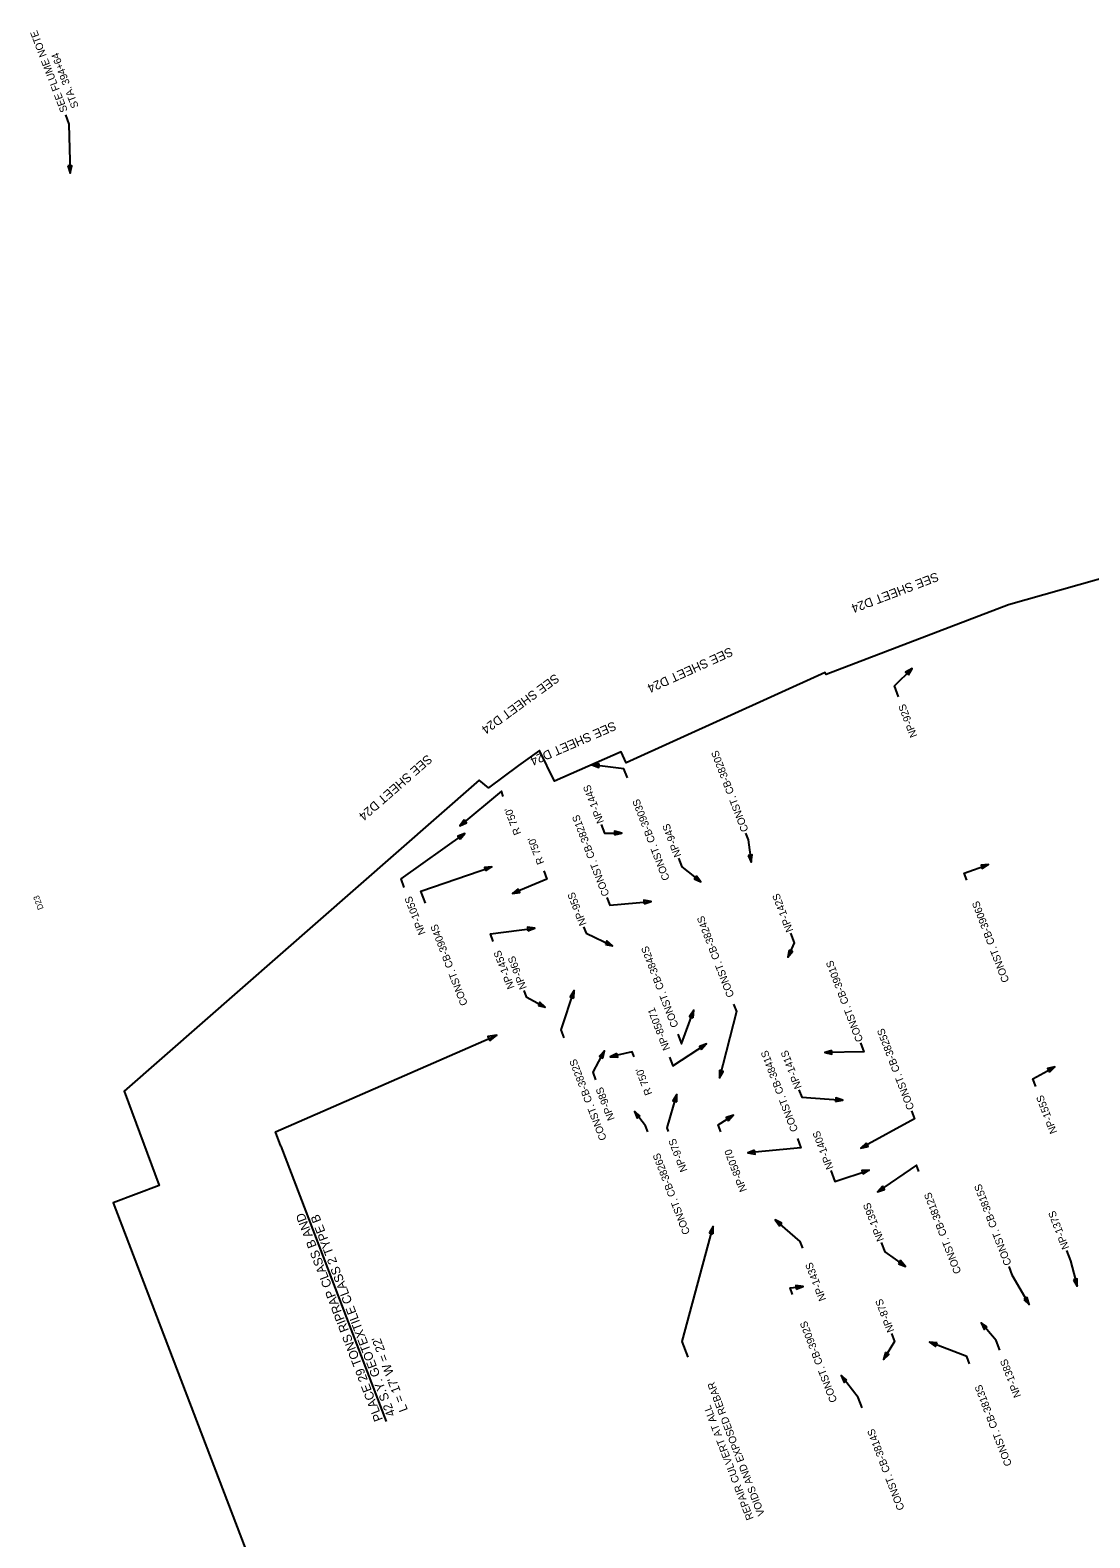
# Model space of a CAD drawing. Extents: x 1611058 to 1612754, y 1091411 to 1093437.
# Drawn here: x 1611058 to 1611771, y 1092422 to 1093437 of the extents above; entities that cross this region are included whole.
import ezdxf

# ---------------------------------------------------------------- set-up
doc = ezdxf.new("R2010")
doc.units = 0
for name, color, linetype in [('BR_CONCRETE', 7, 'Continuous'), ('RD_HC_CL', 7, 'Continuous'), ('RD_HY_Area_XP-Post sub TXT', 7, 'Continuous'), ('RD_HY_Misc', 7, 'Continuous')]:
    doc.layers.add(name, color=color, linetype=linetype)

msp = doc.modelspace()

# ---------------------------------------------------------------- linework, layer by layer
at = {"layer": 'BR_CONCRETE'}
msp.add_line((1611227, 1092685.9), (1611297.8, 1092500.6), dxfattribs=at)
for points in [[(1611082, 1093379.7), (1611084.3, 1093373.4), (1611085.1, 1093340.5)], [(1611642.6, 1092988.1), (1611639.8, 1092995.5), (1611651.7, 1093007.2)], [(1611460.1, 1092933.6), (1611457.7, 1092939.8), (1611436.2, 1092942.4)], [(1611376.6, 1092921.1), (1611375.3, 1092924.6), (1611347.4, 1092901.3)], [(1611442.5, 1092902.2), (1611444.8, 1092896.4), (1611456.3, 1092896.5)], [(1611310, 1092859.9), (1611307.8, 1092865.6), (1611350.7, 1092896.3)], [(1611539.7, 1092896.5), (1611541.5, 1092891.9), (1611543.4, 1092876.9)], [(1611324.2, 1092849.3), (1611321.1, 1092857.4), (1611369, 1092873.8)], [(1611403.8, 1092871), (1611405.9, 1092865.5), (1611382.8, 1092855.8)], [(1611494.5, 1092879.6), (1611496.8, 1092873.7), (1611509.5, 1092863.6)], [(1611688.5, 1092864.9), (1611686.8, 1092869.6), (1611703.1, 1092875.3)], [(1611446.2, 1092853.2), (1611448.2, 1092848), (1611476.2, 1092850.5)], [(1611369.9, 1092823.5), (1611367.9, 1092828.6), (1611397.8, 1092832.6)], [(1611430.7, 1092833.4), (1611432.3, 1092829.2), (1611450.2, 1092820.6)], [(1611569.8, 1092829.2), (1611572.3, 1092822.7), (1611568.1, 1092812.9)], [(1611390.5, 1092790.5), (1611392.1, 1092786.4), (1611404.8, 1092779.3)], [(1611417.6, 1092758.7), (1611415.6, 1092764.1), (1611424.4, 1092790.5)], [(1611531.6, 1092781.5), (1611533.5, 1092776.5), (1611522, 1092731.9)], [(1611494.1, 1092761.3), (1611496.6, 1092754.6), (1611504.8, 1092777.3)], [(1611227, 1092685.9), (1611223.3, 1092695.6), (1611372.2, 1092760.6)], [(1611439, 1092730.4), (1611437, 1092735.7), (1611444.7, 1092749.9)], [(1611464.7, 1092745.9), (1611463.4, 1092749.4), (1611448.6, 1092745.9)], [(1611488.4, 1092745.8), (1611490.7, 1092739.8), (1611513.4, 1092754.6)], [(1611617, 1092755.3), (1611619.2, 1092749.3), (1611592.9, 1092748.9)], [(1611735, 1092726.1), (1611733, 1092731.1), (1611747.8, 1092739.2)], [(1611487.9, 1092695.7), (1611487, 1092698.1), (1611493.4, 1092720.6)], [(1611575.6, 1092723.7), (1611577.4, 1092718.9), (1611605.1, 1092716.7)], [(1611473.8, 1092695.4), (1611472.3, 1092699.5), (1611464.9, 1092709.2)], [(1611651.3, 1092709.6), (1611653.4, 1092704.2), (1611617.3, 1092684.5)], [(1611522.9, 1092695.5), (1611521.1, 1092700.3), (1611531.5, 1092706.6)], [(1611574.5, 1092691), (1611576.9, 1092684.8), (1611541.1, 1092681.3)], [(1611597, 1092669.5), (1611599.8, 1092662), (1611622.9, 1092669.8)], [(1611656.3, 1092668.9), (1611654.7, 1092673), (1611628.5, 1092655.2)], [(1611501, 1092544), (1611497, 1092554.5), (1611517.9, 1092631.8)], [(1611578.1, 1092617.3), (1611576.4, 1092621.7), (1611559.6, 1092636.3)], [(1611630.9, 1092621), (1611633.3, 1092614.8), (1611647.2, 1092605)], [(1611755.5, 1092615.6), (1611758.2, 1092608.8), (1611762.8, 1092591.7)], [(1611716.7, 1092604.9), (1611718.9, 1092599.2), (1611730.4, 1092579.3)], [(1611571.3, 1092586.1), (1611569.6, 1092590.6), (1611578.3, 1092591.4)], [(1611710.7, 1092548.6), (1611708.2, 1092555.1), (1611698.1, 1092567.1)], [(1611637.8, 1092559.9), (1611639.9, 1092554.5), (1611632.5, 1092542.3)], [(1611690.3, 1092539.5), (1611688.5, 1092544.4), (1611663.5, 1092554)], [(1611618.1, 1092509.8), (1611615.4, 1092516.8), (1611603.9, 1092531.5)]]:
    msp.add_lwpolyline(points, dxfattribs=at)
for points in [[(1611083.7, 1093345.3), (1611085.1, 1093340.5), (1611086.3, 1093345.3)], [(1611649.2, 1093002.9), (1611651.7, 1093007.2), (1611647.3, 1093004.7)], [(1611441.1, 1092943.1), (1611436.2, 1092942.4), (1611440.8, 1092940.6)], [(1611350.3, 1092905.4), (1611347.4, 1092901.3), (1611351.9, 1092903.4)], [(1611347.6, 1092892.4), (1611350.7, 1092896.3), (1611346.1, 1092894.5)], [(1611451.5, 1092895.2), (1611456.3, 1092896.5), (1611451.4, 1092897.8)], [(1611541.5, 1092881.5), (1611543.4, 1092876.9), (1611544.1, 1092881.9)], [(1611364.9, 1092871), (1611369, 1092873.8), (1611364, 1092873.4)], [(1611698.9, 1092872.5), (1611703.1, 1092875.3), (1611698.1, 1092874.9)], [(1611505, 1092865.6), (1611509.5, 1092863.6), (1611506.6, 1092867.6)], [(1611386.7, 1092858.9), (1611382.8, 1092855.8), (1611387.7, 1092856.5)], [(1611471.5, 1092848.8), (1611476.2, 1092850.5), (1611471.2, 1092851.3)], [(1611393.2, 1092830.7), (1611397.8, 1092832.6), (1611392.9, 1092833.3)], [(1611445.3, 1092821.5), (1611450.2, 1092820.6), (1611446.4, 1092823.9)], [(1611568.9, 1092817.8), (1611568.1, 1092812.9), (1611571.2, 1092816.8)], [(1611424.1, 1092785.5), (1611424.4, 1092790.5), (1611421.7, 1092786.3)], [(1611400, 1092780.5), (1611404.8, 1092779.3), (1611401.2, 1092782.7)], [(1611504.4, 1092772.3), (1611504.8, 1092777.3), (1611501.9, 1092773.2)], [(1611367.5, 1092756.8), (1611372.2, 1092760.6), (1611366.2, 1092759.7)], [(1611443.6, 1092745), (1611444.7, 1092749.9), (1611441.3, 1092746.3)], [(1611453, 1092748.3), (1611448.6, 1092745.9), (1611453.6, 1092745.8)], [(1611510.1, 1092750.8), (1611513.4, 1092754.6), (1611508.6, 1092753)], [(1611597.7, 1092750.2), (1611592.9, 1092748.9), (1611597.7, 1092747.7)], [(1611744.2, 1092735.7), (1611747.8, 1092739.2), (1611742.9, 1092738)], [(1611522, 1092736.9), (1611522, 1092731.9), (1611524.5, 1092736.2)], [(1611493.3, 1092715.6), (1611493.4, 1092720.6), (1611490.8, 1092716.3)], [(1611600.1, 1092715.8), (1611605.1, 1092716.7), (1611600.4, 1092718.4)], [(1611468.8, 1092706.1), (1611464.9, 1092709.2), (1611466.8, 1092704.6)], [(1611528.1, 1092703), (1611531.5, 1092706.6), (1611526.7, 1092705.2)], [(1611620.9, 1092687.9), (1611617.3, 1092684.5), (1611622.1, 1092685.7)], [(1611545.7, 1092683.1), (1611541.1, 1092681.3), (1611546, 1092680.5)], [(1611618.7, 1092667.1), (1611622.9, 1092669.8), (1611617.9, 1092669.5)], [(1611631.8, 1092659), (1611628.5, 1092655.2), (1611633.2, 1092656.8)], [(1611517.9, 1092626.8), (1611517.9, 1092631.8), (1611515.4, 1092627.5)], [(1611564.1, 1092634.1), (1611559.6, 1092636.3), (1611562.4, 1092632.2)], [(1611642.5, 1092606.7), (1611647.2, 1092605), (1611644, 1092608.9)], [(1611760.3, 1092596), (1611762.8, 1092591.7), (1611762.8, 1092596.7)], [(1611573.6, 1092589.7), (1611578.3, 1092591.4), (1611573.4, 1092592.2)], [(1611726.9, 1092582.8), (1611730.4, 1092579.3), (1611729.1, 1092584.1)], [(1611702.2, 1092564.2), (1611698.1, 1092567.1), (1611700.2, 1092562.6)], [(1611633.9, 1092547.1), (1611632.5, 1092542.3), (1611636.1, 1092545.8)], [(1611668.5, 1092553.5), (1611663.5, 1092554), (1611667.5, 1092551.1)], [(1611607.9, 1092528.5), (1611603.9, 1092531.5), (1611605.9, 1092526.9)]]:
    msp.add_lwpolyline(points, close=True, dxfattribs=at)
at = {"layer": 'RD_HY_Misc'}
msp.add_lwpolyline([(1612477.1, 1091747.5), (1611951.2, 1093116.5), (1611716.5, 1093050), (1611593.8, 1093003.2), (1611593.2, 1093004.6), (1611459.3, 1092943.8), (1611456, 1092951.1), (1611411, 1092931.5), (1611401, 1092952), (1611386.8, 1092942), (1611366.6, 1092927), (1611360.4, 1092932), (1611304.4, 1092882.9), (1611121.4, 1092722.8), (1611145.1, 1092659.4), (1611114.1, 1092647.8), (1611496.9, 1091646.4)], dxfattribs=at)
msp.add_lwpolyline([(1612477.1, 1091747.5), (1611951.2, 1093116.5), (1611716.5, 1093050), (1611593.8, 1093003.2), (1611593.2, 1093004.6), (1611459.3, 1092943.8), (1611456, 1092951.1), (1611411, 1092931.5), (1611401, 1092952), (1611386.8, 1092942), (1611366.6, 1092927), (1611360.4, 1092932), (1611304.4, 1092882.9), (1611121.4, 1092722.8), (1611145.1, 1092659.4), (1611114.1, 1092647.8), (1611496.9, 1091646.4)], dxfattribs=at)

# ---------------------------------------------------------------- texts
at = {"layer": 'BR_CONCRETE'}
for s, height, p in [('SEE FLUME NOTE', 5, (1611083.6, 1093382.5)), ('STA. 394+64', 5, (1611091, 1093385.3)), ('NP-92S', 5, (1611655.3, 1092961.9)), ('CONST. CB-3820S', 5, (1611541.7, 1092898.4)), ('NP-144S', 5, (1611444.5, 1092904.1)), ("R 750'", 5, (1611388.7, 1092896.3)), ('CONST. CB-3903S', 5, (1611488.7, 1092865.7)), ('CONST. CB-3821S', 5, (1611448.1, 1092855.1)), ('NP-94S', 5, (1611496.5, 1092881.4)), ("R 750'", 5, (1611404.3, 1092876.5)), ('NP-105S', 5, (1611324.4, 1092829.1)), ('NP-95S', 5, (1611432.7, 1092835.3)), ('NP-142S', 5, (1611571.8, 1092831)), ('CONST. CB-3906S', 5, (1611717.2, 1092797.1)), ('CONST. CB-3824S', 5, (1611532.1, 1092787.1)), ('CONST. CB-3904S', 5, (1611352.8, 1092781.5)), ('CONST. CB-3842S', 5, (1611494.6, 1092766.8)), ('NP-145S', 5, (1611384.3, 1092792.7)), ('NP-96S', 5, (1611392.5, 1092792.4)), ('CONST. CB-3901S', 5, (1611618.9, 1092757.1)), ('NP-85071', 5, (1611489, 1092751.4)), ('CONST. CB-3825S', 5, (1611653.3, 1092711.4)), ('CONST. CB-3841S', 5, (1611575.1, 1092696.6)), ('NP-141S', 5, (1611577.5, 1092725.5)), ('CONST. CB-3822S', 5, (1611446.3, 1092690.8)), ("R 750'", 5, (1611476.9, 1092721.2)), ('NP-98S', 5, (1611451.7, 1092704.2)), ('NP-155S', 5, (1611749.4, 1092695.3)), ('NP-97S', 5, (1611500.6, 1092669.6)), ('NP-140S', 5, (1611598.9, 1092671.3)), ('CONST. CB-3826S', 5, (1611502.4, 1092627.5)), ('NP-85070', 5, (1611540.6, 1092656.2)), ('CONST. CB-3815S', 5, (1611718.7, 1092606.7)), ('NP-139S', 5, (1611632.9, 1092622.9)), ('CONST. CB-3812S', 5, (1611684.9, 1092601.1)), ('PLACE 29 TONS RIPRAP CLASS B AND', 6, (1611295.7, 1092502)), ('42 S.Y. GEOTEXTILE CLASS 2 TYPE B', 6, (1611304.1, 1092505.2)), ('NP-137S', 5, (1611757.5, 1092617.5)), ('NP-143S', 5, (1611594, 1092582.8)), ('NP-87S', 5, (1611639.8, 1092561.7)), ('CONST. CB-3902S', 5, (1611601.4, 1092514.5)), ("L = 17' W = 22'", 6, (1611312.5, 1092508.4)), ('NP-138S', 5, (1611725.1, 1092517.8)), ('VOIDS AND EXPOSED REBAR', 5, (1611552.7, 1092438.2)), ('CONST. CB-3813S', 5, (1611719, 1092471.7)), ('REPAIR CULVERT AT ALL', 5, (1611545.2, 1092435.4)), ('CONST. CB-3814S', 5, (1611646.7, 1092442))]:
    msp.add_text(s, height=height, rotation=110.9145, dxfattribs=at).set_placement(p)
at = {"layer": 'RD_HC_CL'}
msp.add_text('D23', height=4, rotation=110.9145, dxfattribs=at).set_placement((1611067.4, 1092845.8))
at = {"layer": 'RD_HY_Area_XP-Post sub TXT'}
for rotation, p in [(200.8649, (1611668.2, 1093072.1)), (204.4049, (1611529.4, 1093021.7)), (216.0552, (1611411.5, 1093004)), (203.4637, (1611451, 1092971.8)), (221.2017, (1611325.5, 1092949.7))]:
    msp.add_text('SEE SHEET D24', height=6, rotation=rotation, dxfattribs=at).set_placement(p)

doc.saveas('drawing.dxf')
